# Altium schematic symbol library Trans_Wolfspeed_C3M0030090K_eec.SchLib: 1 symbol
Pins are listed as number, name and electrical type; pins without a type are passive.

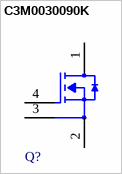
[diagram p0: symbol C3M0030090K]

## C3M0030090K
designator Q?  (value not drawn)
pins: 1 Drain, 2 Power Source, 3 Driver Source, 4 Gate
